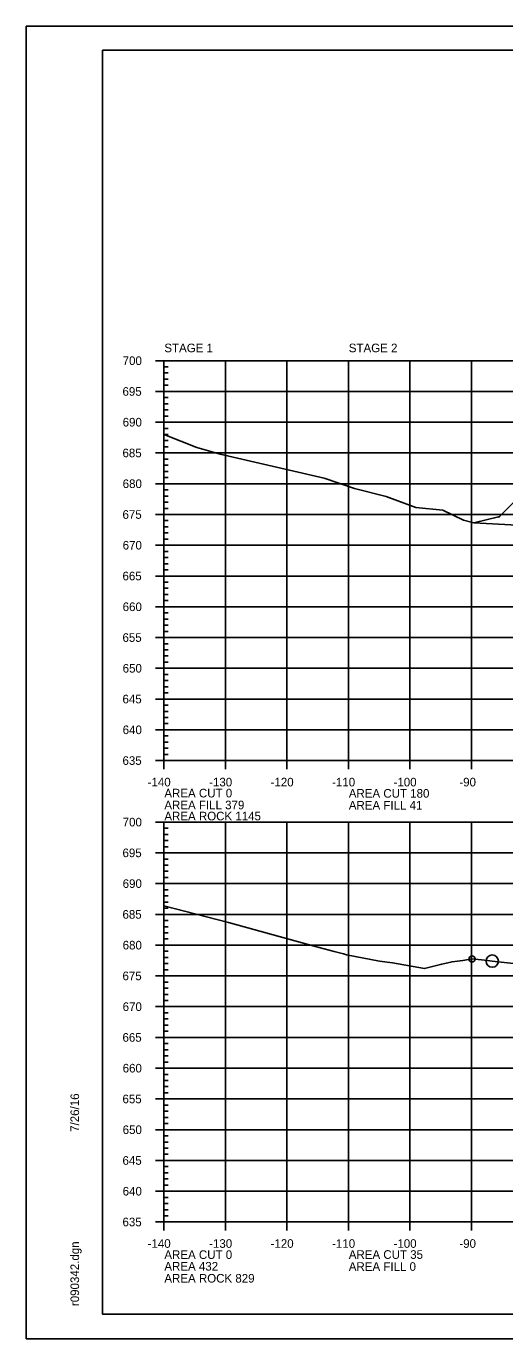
# Model space of a CAD drawing. Extents: x 1370515 to 1370849, y 383299 to 386073.
# Drawn here: x 1370515.4 to 1370593.2, y 384792.8 to 385006.1 of the extents above; entities that cross this region are included whole.
import ezdxf

# ---------------------------------------------------------------- set-up
doc = ezdxf.new("R2010")
doc.units = 0
for name, color, linetype in [('R_Axis', 7, 'Continuous'), ('R_Axis Annot', 7, 'Continuous'), ('R_Border', 7, 'Continuous'), ('R_Exist Surface', 7, 'Continuous'), ('R_Fin Surface', 7, 'Continuous'), ('R_Grid', 7, 'Continuous'), ('R_No Plot', 7, 'Continuous')]:
    doc.layers.add(name, color=color, linetype=linetype)

msp = doc.modelspace()

# ---------------------------------------------------------------- linework, layer by layer
at = {"layer": 'R_Axis'}
for p, q in [((1370536.4, 384951.77), (1370539.2, 384951.77)), ((1370537.8, 384886.77), (1370537.8, 384951.77)), ((1370537.8, 384950.77), (1370538.5, 384950.77)), ((1370537.8, 384949.77), (1370538.5, 384949.77)), ((1370537.8, 384948.77), (1370538.5, 384948.77)), ((1370536.4, 384946.77), (1370539.2, 384946.77)), ((1370537.8, 384947.77), (1370538.5, 384947.77)), ((1370537.8, 384945.77), (1370538.5, 384945.77)), ((1370537.8, 384944.77), (1370538.5, 384944.77)), ((1370537.8, 384943.77), (1370538.5, 384943.77)), ((1370537.8, 384942.77), (1370538.5, 384942.77)), ((1370536.4, 384941.77), (1370539.2, 384941.77)), ((1370537.8, 384940.77), (1370538.5, 384940.77)), ((1370537.8, 384939.77), (1370538.5, 384939.77)), ((1370537.8, 384938.77), (1370538.5, 384938.77)), ((1370536.4, 384936.77), (1370539.2, 384936.77)), ((1370537.8, 384937.77), (1370538.5, 384937.77)), ((1370537.8, 384935.77), (1370538.5, 384935.77)), ((1370537.8, 384934.77), (1370538.5, 384934.77)), ((1370537.8, 384933.77), (1370538.5, 384933.77)), ((1370536.4, 384931.77), (1370539.2, 384931.77)), ((1370537.8, 384932.77), (1370538.5, 384932.77)), ((1370537.8, 384930.77), (1370538.5, 384930.77)), ((1370537.8, 384929.77), (1370538.5, 384929.77)), ((1370537.8, 384928.77), (1370538.5, 384928.77)), ((1370537.8, 384927.77), (1370538.5, 384927.77)), ((1370536.4, 384926.77), (1370539.2, 384926.77)), ((1370537.8, 384925.77), (1370538.5, 384925.77)), ((1370537.8, 384924.77), (1370538.5, 384924.77)), ((1370537.8, 384923.77), (1370538.5, 384923.77)), ((1370536.4, 384921.77), (1370539.2, 384921.77)), ((1370537.8, 384922.77), (1370538.5, 384922.77)), ((1370537.8, 384920.77), (1370538.5, 384920.77)), ((1370537.8, 384919.77), (1370538.5, 384919.77)), ((1370537.8, 384918.77), (1370538.5, 384918.77)), ((1370536.4, 384916.77), (1370539.2, 384916.77)), ((1370537.8, 384917.77), (1370538.5, 384917.77)), ((1370537.8, 384915.77), (1370538.5, 384915.77)), ((1370537.8, 384914.77), (1370538.5, 384914.77)), ((1370537.8, 384913.77), (1370538.5, 384913.77)), ((1370537.8, 384912.77), (1370538.5, 384912.77)), ((1370536.4, 384911.77), (1370539.2, 384911.77)), ((1370537.8, 384910.77), (1370538.5, 384910.77)), ((1370537.8, 384909.77), (1370538.5, 384909.77)), ((1370537.8, 384908.77), (1370538.5, 384908.77)), ((1370536.4, 384906.77), (1370539.2, 384906.77)), ((1370537.8, 384907.77), (1370538.5, 384907.77)), ((1370537.8, 384905.77), (1370538.5, 384905.77)), ((1370537.8, 384904.77), (1370538.5, 384904.77)), ((1370537.8, 384903.77), (1370538.5, 384903.77)), ((1370536.4, 384901.77), (1370539.2, 384901.77)), ((1370537.8, 384902.77), (1370538.5, 384902.77)), ((1370537.8, 384900.77), (1370538.5, 384900.77)), ((1370537.8, 384899.77), (1370538.5, 384899.77)), ((1370537.8, 384898.77), (1370538.5, 384898.77)), ((1370537.8, 384897.77), (1370538.5, 384897.77)), ((1370536.4, 384896.77), (1370539.2, 384896.77)), ((1370537.8, 384895.77), (1370538.5, 384895.77)), ((1370537.8, 384894.77), (1370538.5, 384894.77)), ((1370537.8, 384893.77), (1370538.5, 384893.77)), ((1370536.4, 384891.77), (1370539.2, 384891.77)), ((1370537.8, 384892.77), (1370538.5, 384892.77)), ((1370537.8, 384890.77), (1370538.5, 384890.77)), ((1370537.8, 384889.77), (1370538.5, 384889.77)), ((1370537.8, 384888.77), (1370538.5, 384888.77)), ((1370536.4, 384886.77), (1370539.2, 384886.77)), ((1370537.8, 384885.37), (1370537.8, 384888.17)), ((1370537.8, 384887.77), (1370538.5, 384887.77)), ((1370537.8, 384886.77), (1370817.8, 384886.77)), ((1370547.8, 384885.37), (1370547.8, 384888.17)), ((1370557.8, 384885.37), (1370557.8, 384888.17)), ((1370567.8, 384885.37), (1370567.8, 384888.17)), ((1370577.8, 384885.37), (1370577.8, 384888.17)), ((1370587.8, 384885.37), (1370587.8, 384888.17)), ((1370536.4, 384876.77), (1370539.2, 384876.77)), ((1370537.8, 384811.77), (1370537.8, 384876.77)), ((1370537.8, 384875.77), (1370538.5, 384875.77)), ((1370537.8, 384874.77), (1370538.5, 384874.77)), ((1370536.4, 384871.77), (1370539.2, 384871.77)), ((1370537.8, 384873.77), (1370538.5, 384873.77)), ((1370537.8, 384872.77), (1370538.5, 384872.77)), ((1370537.8, 384870.77), (1370538.5, 384870.77)), ((1370537.8, 384869.77), (1370538.5, 384869.77)), ((1370537.8, 384868.77), (1370538.5, 384868.77)), ((1370537.8, 384867.77), (1370538.5, 384867.77)), ((1370536.4, 384866.77), (1370539.2, 384866.77)), ((1370537.8, 384865.77), (1370538.5, 384865.77)), ((1370537.8, 384864.77), (1370538.5, 384864.77)), ((1370537.8, 384863.77), (1370538.5, 384863.77)), ((1370536.4, 384861.77), (1370539.2, 384861.77)), ((1370537.8, 384862.77), (1370538.5, 384862.77)), ((1370537.8, 384860.77), (1370538.5, 384860.77)), ((1370537.8, 384859.77), (1370538.5, 384859.77)), ((1370536.4, 384856.77), (1370539.2, 384856.77)), ((1370537.8, 384858.77), (1370538.5, 384858.77)), ((1370537.8, 384857.77), (1370538.5, 384857.77)), ((1370537.8, 384855.77), (1370538.5, 384855.77)), ((1370537.8, 384854.77), (1370538.5, 384854.77)), ((1370537.8, 384853.77), (1370538.5, 384853.77)), ((1370537.8, 384852.77), (1370538.5, 384852.77)), ((1370536.4, 384851.77), (1370539.2, 384851.77)), ((1370537.8, 384850.77), (1370538.5, 384850.77)), ((1370537.8, 384849.77), (1370538.5, 384849.77)), ((1370537.8, 384848.77), (1370538.5, 384848.77)), ((1370536.4, 384846.77), (1370539.2, 384846.77)), ((1370537.8, 384847.77), (1370538.5, 384847.77)), ((1370537.8, 384845.77), (1370538.5, 384845.77)), ((1370537.8, 384844.77), (1370538.5, 384844.77)), ((1370537.8, 384843.77), (1370538.5, 384843.77)), ((1370537.8, 384842.77), (1370538.5, 384842.77)), ((1370536.4, 384841.77), (1370539.2, 384841.77)), ((1370537.8, 384840.77), (1370538.5, 384840.77)), ((1370537.8, 384839.77), (1370538.5, 384839.77)), ((1370537.8, 384838.77), (1370538.5, 384838.77)), ((1370537.8, 384837.77), (1370538.5, 384837.77)), ((1370536.4, 384836.77), (1370539.2, 384836.77)), ((1370537.8, 384835.77), (1370538.5, 384835.77)), ((1370537.8, 384834.77), (1370538.5, 384834.77)), ((1370537.8, 384833.77), (1370538.5, 384833.77)), ((1370536.4, 384831.77), (1370539.2, 384831.77)), ((1370537.8, 384832.77), (1370538.5, 384832.77)), ((1370537.8, 384830.77), (1370538.5, 384830.77)), ((1370537.8, 384829.77), (1370538.5, 384829.77)), ((1370537.8, 384828.77), (1370538.5, 384828.77)), ((1370537.8, 384827.77), (1370538.5, 384827.77)), ((1370536.4, 384826.77), (1370539.2, 384826.77)), ((1370537.8, 384825.77), (1370538.5, 384825.77)), ((1370537.8, 384824.77), (1370538.5, 384824.77)), ((1370537.8, 384823.77), (1370538.5, 384823.77)), ((1370537.8, 384822.77), (1370538.5, 384822.77)), ((1370536.4, 384821.77), (1370539.2, 384821.77)), ((1370537.8, 384820.77), (1370538.5, 384820.77)), ((1370537.8, 384819.77), (1370538.5, 384819.77)), ((1370537.8, 384818.77), (1370538.5, 384818.77)), ((1370536.4, 384816.77), (1370539.2, 384816.77)), ((1370537.8, 384817.77), (1370538.5, 384817.77)), ((1370537.8, 384815.77), (1370538.5, 384815.77)), ((1370537.8, 384814.77), (1370538.5, 384814.77)), ((1370537.8, 384813.77), (1370538.5, 384813.77)), ((1370537.8, 384810.37), (1370537.8, 384813.17)), ((1370537.8, 384812.77), (1370538.5, 384812.77)), ((1370547.8, 384810.37), (1370547.8, 384813.17)), ((1370557.8, 384810.37), (1370557.8, 384813.17)), ((1370567.8, 384810.37), (1370567.8, 384813.17)), ((1370577.8, 384810.37), (1370577.8, 384813.17)), ((1370587.8, 384810.37), (1370587.8, 384813.17)), ((1370536.4, 384811.77), (1370539.2, 384811.77)), ((1370537.8, 384811.77), (1370817.8, 384811.77))]:
    msp.add_line(p, q, dxfattribs=at)
at = {"layer": 'R_Border'}
for p, q in [((1370527.8, 385002.23), (1370843.98, 385002.23)), ((1370527.8, 384796.77), (1370527.8, 385002.23)), ((1370527.8, 384796.77), (1370527.8, 384796.77)), ((1370843.98, 384796.77), (1370527.8, 384796.77))]:
    msp.add_line(p, q, dxfattribs=at)
at = {"layer": 'R_Exist Surface'}
for points in [[(1370537.8, 384939.75), (1370537.92, 384939.72), (1370543.16, 384937.67), (1370546.93, 384936.6), (1370563.87, 384932.65), (1370568.78, 384931.02), (1370573.95, 384929.68), (1370578.76, 384927.92), (1370583.14, 384927.46), (1370586.5, 384925.87), (1370588.17, 384925.44), (1370592.23, 384926.39), (1370592.33, 384926.35), (1370592.36, 384926.41), (1370592.37, 384926.47), (1370592.43, 384926.52), (1370595.72, 384929.79)], [(1370537.8, 384863.14), (1370548.27, 384860.45), (1370562.2, 384856.62), (1370565.48, 384855.72), (1370566.98, 384855.34), (1370567.5, 384855.2), (1370572.83, 384854.17), (1370574.98, 384853.88), (1370580.16, 384852.97), (1370582.97, 384853.68), (1370584.66, 384854.06), (1370586.43, 384854.3), (1370587.92, 384854.53), (1370590.41, 384854.26), (1370591.2, 384854.18), (1370595.11, 384853.75)]]:
    msp.add_lwpolyline(points, dxfattribs=at)
at = {"layer": 'R_Fin Surface'}
msp.add_lwpolyline([(1370588.17, 384925.44), (1370626.49, 384923.33), (1370651.8, 384931.77), (1370657.8, 384933.27), (1370665.8, 384932.51), (1370677.8, 384931.36), (1370689.8, 384930.21), (1370697.8, 384929.45), (1370703.8, 384927.95), (1370708.72, 384925.49), (1370755.19, 384902.25)], dxfattribs=at)
at = {"layer": 'R_Grid'}
for p, q in [((1370537.8, 384951.77), (1370817.8, 384951.77)), ((1370537.8, 384886.77), (1370537.8, 384951.77)), ((1370547.8, 384886.77), (1370547.8, 384951.77)), ((1370557.8, 384886.77), (1370557.8, 384951.77)), ((1370567.8, 384886.77), (1370567.8, 384951.77)), ((1370577.8, 384886.77), (1370577.8, 384951.77)), ((1370587.8, 384886.77), (1370587.8, 384951.77)), ((1370537.8, 384946.77), (1370817.8, 384946.77)), ((1370537.8, 384941.77), (1370817.8, 384941.77)), ((1370537.8, 384936.77), (1370817.8, 384936.77)), ((1370537.8, 384931.77), (1370817.8, 384931.77)), ((1370537.8, 384926.77), (1370817.8, 384926.77)), ((1370537.8, 384921.77), (1370817.8, 384921.77)), ((1370537.8, 384916.77), (1370817.8, 384916.77)), ((1370537.8, 384911.77), (1370817.8, 384911.77)), ((1370537.8, 384906.77), (1370817.8, 384906.77)), ((1370537.8, 384901.77), (1370817.8, 384901.77)), ((1370537.8, 384896.77), (1370817.8, 384896.77)), ((1370537.8, 384891.77), (1370817.8, 384891.77)), ((1370537.8, 384886.77), (1370817.8, 384886.77)), ((1370537.8, 384876.77), (1370817.8, 384876.77)), ((1370537.8, 384811.77), (1370537.8, 384876.77)), ((1370547.8, 384811.77), (1370547.8, 384876.77)), ((1370557.8, 384811.77), (1370557.8, 384876.77)), ((1370567.8, 384811.77), (1370567.8, 384876.77)), ((1370577.8, 384811.77), (1370577.8, 384876.77)), ((1370587.8, 384811.77), (1370587.8, 384876.77)), ((1370537.8, 384871.77), (1370817.8, 384871.77)), ((1370537.8, 384866.77), (1370817.8, 384866.77)), ((1370537.8, 384861.77), (1370817.8, 384861.77)), ((1370537.8, 384856.77), (1370817.8, 384856.77)), ((1370537.8, 384851.77), (1370817.8, 384851.77)), ((1370537.8, 384846.77), (1370817.8, 384846.77)), ((1370537.8, 384841.77), (1370817.8, 384841.77)), ((1370537.8, 384836.77), (1370817.8, 384836.77)), ((1370537.8, 384831.77), (1370817.8, 384831.77)), ((1370537.8, 384826.77), (1370817.8, 384826.77)), ((1370537.8, 384821.77), (1370817.8, 384821.77)), ((1370537.8, 384816.77), (1370817.8, 384816.77)), ((1370537.8, 384811.77), (1370817.8, 384811.77))]:
    msp.add_line(p, q, dxfattribs=at)
at = {"layer": 'R_No Plot'}
for p, q in [((1370515.4, 385006.13), (1370848.73, 385006.13)), ((1370515.4, 384792.8), (1370848.73, 384792.8))]:
    msp.add_line(p, q, dxfattribs=at)
for points in [[(1370515.39, 385006.13), (1370848.73, 385006.13), (1370848.73, 384792.79), (1370515.39, 384792.79)], [(1370761.72, 385002.23), (1370761.72, 384992.35), (1370797.45, 384992.35), (1370797.45, 384989.43), (1370820.65, 384989.43), (1370820.65, 384966.22), (1370843.98, 384966.22), (1370843.98, 384796.77), (1370527.8, 384796.77), (1370527.8, 385002.23)]]:
    msp.add_lwpolyline(points, close=True, dxfattribs=at)
for centre, radius in [((1370587.92, 384854.53), 0.5), ((1370591.2, 384854.18), 1)]:
    msp.add_circle(centre, radius, dxfattribs=at)

# ---------------------------------------------------------------- texts
at = {"layer": 'R_Axis'}
for p in [(1370537.8, 384886.77), (1370537.8, 384811.77)]:
    msp.add_text('-', height=0.0001, dxfattribs=at).set_placement(p)
at = {"layer": 'R_Axis Annot'}
for s, p in [('STAGE 1', (1370537.86, 384953.14)), ('STAGE 2', (1370567.86, 384953.14)), ('700', (1370531.08, 384951.07)), ('695', (1370531.05, 384946.07)), ('690', (1370531.08, 384941.07)), ('685', (1370531.05, 384936.07)), ('680', (1370531.08, 384931.07)), ('675', (1370531.05, 384926.07)), ('670', (1370531.08, 384921.07)), ('665', (1370531.05, 384916.07)), ('660', (1370531.08, 384911.07)), ('655', (1370531.05, 384906.07)), ('650', (1370531.08, 384901.07)), ('645', (1370531.05, 384896.07)), ('640', (1370531.08, 384891.07)), ('635', (1370531.05, 384886.07)), ('-140', (1370535.14, 384882.57)), ('-130', (1370545.14, 384882.57)), ('-120', (1370555.14, 384882.57)), ('-110', (1370565.14, 384882.57)), ('-100', (1370575.14, 384882.57)), ('-90', (1370585.84, 384882.57)), ('AREA CUT 0', (1370537.86, 384880.78)), ('AREA FILL 379', (1370537.86, 384878.85)), ('AREA CUT 180', (1370567.86, 384880.74)), ('AREA ROCK 1145', (1370537.86, 384877.05)), ('AREA FILL 41', (1370567.86, 384878.81)), ('700', (1370531.08, 384876.07)), ('695', (1370531.05, 384871.07)), ('690', (1370531.08, 384866.07)), ('685', (1370531.05, 384861.07)), ('680', (1370531.08, 384856.07)), ('675', (1370531.05, 384851.07)), ('670', (1370531.08, 384846.07)), ('665', (1370531.05, 384841.07)), ('660', (1370531.08, 384836.07)), ('655', (1370531.05, 384831.07)), ('650', (1370531.08, 384826.07)), ('645', (1370531.05, 384821.07)), ('640', (1370531.08, 384816.07)), ('635', (1370531.05, 384811.07)), ('-140', (1370535.14, 384807.57)), ('-130', (1370545.14, 384807.57)), ('-120', (1370555.14, 384807.57)), ('-110', (1370565.14, 384807.57)), ('-100', (1370575.14, 384807.57)), ('-90', (1370585.84, 384807.57)), ('AREA CUT 0', (1370537.86, 384805.76)), ('AREA CUT 35', (1370567.86, 384805.78)), ('AREA 432', (1370537.86, 384803.87)), ('AREA FILL 0', (1370567.86, 384803.83)), ('AREA ROCK 829', (1370537.86, 384801.92))]:
    msp.add_text(s, height=1.4, dxfattribs=at).set_placement(p)
at = {"layer": 'R_Border'}
for s, p in [('7/26/16', (1370523.99, 384826.42)), ('r090342.dgn', (1370523.99, 384798.1))]:
    msp.add_text(s, height=1.4, rotation=90, dxfattribs=at).set_placement(p)
at = {"layer": 'R_No Plot'}
for p in [(1370543.12, 384937.62), (1370563.83, 384932.6), (1370592.33, 384926.42), (1370562.16, 384856.57), (1370566.93, 384855.29), (1370572.79, 384854.12), (1370580.12, 384852.92), (1370584.62, 384854.01)]:
    msp.add_text('+', height=0.1, dxfattribs=at).set_placement(p)

doc.saveas('drawing.dxf')
